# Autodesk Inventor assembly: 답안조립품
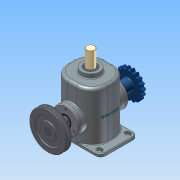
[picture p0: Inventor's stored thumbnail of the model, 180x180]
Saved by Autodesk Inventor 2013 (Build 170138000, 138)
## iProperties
Created: 2014-12
Part Number: 답안조립품
Document SubType Name: Assembly
Designer: Administrator
Mass: 8322.52 g
Surface Area: 4222.88 cm^2
Volume: 1869.1 cm^3
Density: 4.4527 g/cm^3
Author: Administrator
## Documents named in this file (15)
- C:\Users\Administrator\Desktop\341209V1017\답안조립품.iam
- C:\Users\Administrator\Desktop\341209V1017\M4x0.5.ipt
- C:\Users\Administrator\Desktop\341209V1017\V-벨트풀리.ipt
- C:\Users\Administrator\Desktop\341209V1017\멈춤나사 M5x0.5.ipt
- C:\Users\Administrator\Desktop\341209V1017\멈춤링.ipt
- C:\Users\Administrator\Desktop\341209V1017\베어링 6205.ipt
- C:\Users\Administrator\Desktop\341209V1017\본체.ipt
- C:\Users\Administrator\Desktop\341209V1017\부시.ipt
- C:\Users\Administrator\Desktop\341209V1017\슬라이드.ipt
- C:\Users\Administrator\Desktop\341209V1017\오일실.ipt
- C:\Users\Administrator\Desktop\341209V1017\체인 스프로킷.ipt
- C:\Users\Administrator\Desktop\341209V1017\커버.ipt
- C:\Users\Administrator\Desktop\341209V1017\키 8x8.ipt
- C:\Users\Administrator\Desktop\341209V1017\편심축.ipt
- C:\Users\Administrator\Desktop\341209V1017\스프링.ipt
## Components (8 placed, 3 different names)
1. V-벨트풀리:1 — 플러쉬:1, 각도:1
2. 5-체인 스프로킷:1 — 플러쉬:2
3. M4x0.5:4
4. M4x0.5:5
5. M4x0.5:6
6. M4x0.5:1
7. M4x0.5:2
8. M4x0.5:3
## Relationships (3: Flush 2, Angle 1)
- 플러쉬:1 [Flush]: V-벨트풀리:1
- 플러쉬:2 [Flush]: 5-체인 스프로킷:1
- 각도:1 [Angle]: V-벨트풀리:1
